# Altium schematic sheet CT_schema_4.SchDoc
size 293 x 198 mm
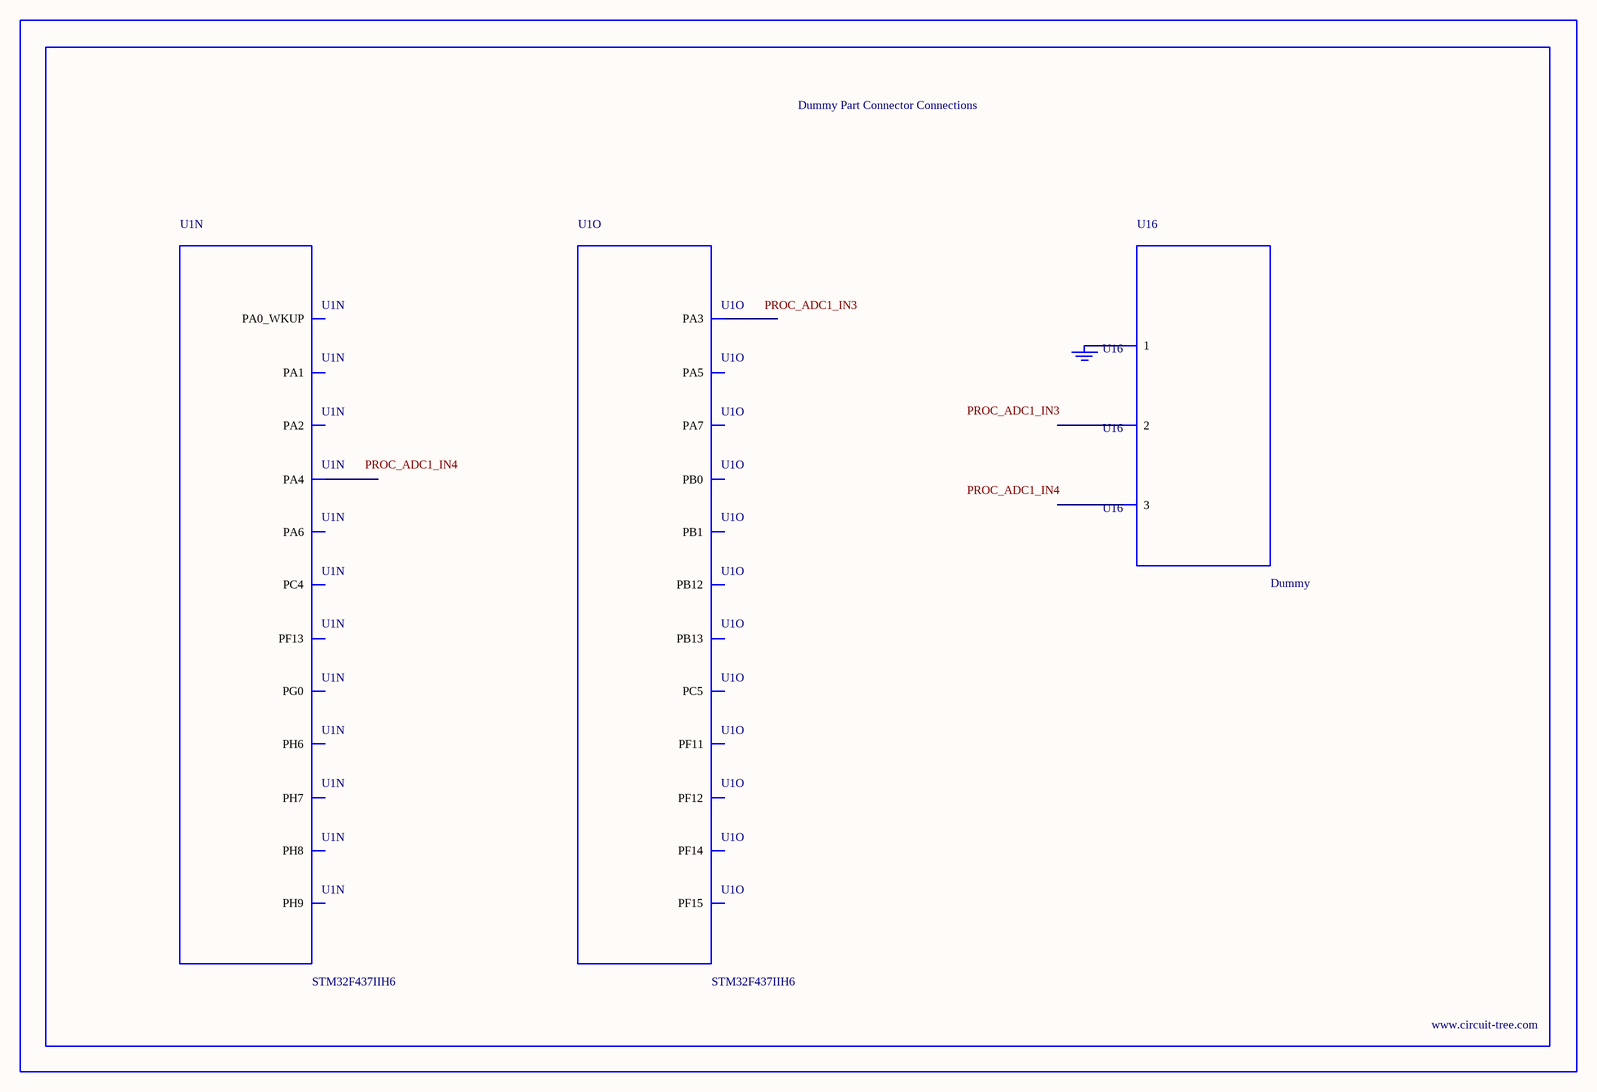
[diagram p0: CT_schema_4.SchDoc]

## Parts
BORDER3  (no value)
GND_INSTANCE_3_0  (no value)
U1  STM32F437IIH6  [UFBGA176_25]  (parts N,O of 15)
U16  Dummy  [DUMMY_PACKAGE_185]

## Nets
NetGND_INSTANCE_3_0_0: GND_INSTANCE_3_0.0(GND) U16.1

Not connected (* = marked no-connect by the designer): U1 M11(PH6) M12(PH8) M13(PH9) N2(PA1) N3(PA0_WKUP) N4(PA4) N5(PC4) N6(PF13) N7(PG0) N12(PH7) P2(PA2) P3(PA6) P4(PA5) P5(PC5) P6(PF12) P7(PF15) P12(PB12) P13(PB13) R2(PA3) R3(PA7) R4(PB1) R5(PB0) R6(PF11) R7(PF14); U16 2 3

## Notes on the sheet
- Labels drawn without touching a wire or pin: PROC_ADC1_IN3, PROC_ADC1_IN4

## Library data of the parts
BORDER3 = BORDER_PAGE3
GND_INSTANCE_3_0 = GND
